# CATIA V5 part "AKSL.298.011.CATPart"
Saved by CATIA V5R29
Part number: АКСЛ.298.011
Definition: Пластина основания
Material "Steel": density 7860 kg/m3, Young's modulus 2e+11 Pa, Poisson ratio 0.266, thermal expansion 1.17e-05 1/K
Bounding box of the stored display mesh (mm): x -75 to 75, y -75 to 75, z 0 to 3
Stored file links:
  Z:\ООО Аксель\Соединения бруса\Соединения бруса\Соединения из листа\АКСЛ.298.010 (Основание)\AKSL.298.011.CATPart
  Z:\ООО Аксель\Соединения бруса\Соединения бруса\Соединения из листа\АКСЛ.298.010 (Основание)\AKSL.298.010.CATProduct
  Z:\#Catalog_GosNIIAS\Holes&Pockets\Part\Соединение шип-паз\Ship-Paz.CATPart
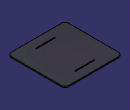
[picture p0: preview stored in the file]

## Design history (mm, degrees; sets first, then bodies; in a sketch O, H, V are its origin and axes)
SheetMetalParameters1: Thickness 3, BendRadius 4, KFactor 0.356492 {= log(min(100,max(20*SheetMetalParameters1.BendRadius,SheetMetalParameters1.Thickness)/SheetMetalParameters1.Thickness))/log(100)/2}, ReliefRadialLength 1, ReliefAxialLength 2, MinimumBendRadius 0
Set1
  DatumCurve1 to DatumCurve3: linked copy from another document
Body1 (main body)
  Pad1: profile DatumCurve1, length 3
  Fillet1: radius 10, on edge [face of Pad1 | face of Pad1] (x4)
  Recognize1: Recognize_BendTable SheetMetalParameters1, Recognize_ReferenceFace end face of Pad1, Recognize_BendDefaultRadius 4, KFacteur 0.356492 {= SheetMetalParameters1.KFactor}
  CutOut1: Direction Sketch1, EndLimit through (limit type 2), Orientation true, Profile Sketch1, StartLimit through (limit type 2)
  SHM_Mirror1: MirroringPlane zx-plane, ObjectToMirror CutOut1
  Sketch1 on DatumCurve2, origin (25, 50, 0), H (-1, 0, 0), V (0, -1, 0)
    reference projected line E1 (0, -2) -> (0, 0) from DatumCurve3
    reference projected line E2 (0, 0) -> (50, 0) from DatumCurve2
    construction line L1 (0, -1) -> (25, -1)
    point P5 (0, -1)
    point P6 (25, -1)
    axis line L2 (25, 0) -> (25, 7.3468)
    point P7 (25, 0)
    line L3 (50.1, -2.1) -> (50.1, 0.1)
    line L4 (50.1, 0.1) -> (-0.1, 0.1)
    line L5 (-0.1, 0.1) -> (-0.1, -2.1)
    line L6 (-0.1, -2.1) -> (50.1, -2.1)
    distance L5 E1 = 0.1
    distance E2 L4 = 0.1
    midpoint: P5 E1, P7 E2
    coincidence: L2 P6
    equidistance: L3 L5 P6, L4 L6 P6
    parallelism: L1 E2, L2 E1, L6 L4, L3 L5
